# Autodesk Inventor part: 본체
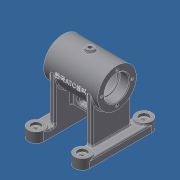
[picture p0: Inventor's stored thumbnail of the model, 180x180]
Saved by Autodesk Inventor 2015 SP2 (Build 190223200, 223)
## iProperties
Created: 2015-11
Part Number: 본체
Material: 일반
Document SubType Name: Modeling
Designer: AMC
Density: 1 g/cm^3
Appearance: 기본값
Author: AMC
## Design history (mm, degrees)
sketch "스케치1"
  geometry: C1 r 25 at (0, 0); 1 further point
  constraints: 1 centre point, 1 coincident
  dimensions: "d0" = 50 diameter of C1
extrude "돌출1" new body sketch "스케치1" stored distance "d1" = 70; taper "d2" = 0 deg
node "작업 평면1"
sketch "스케치2"
  geometry: C1 r 5 at (0, 0); 1 further point
  constraints: 1 centre point, 1 coincident
  dimensions: "d4" = 10 diameter of C1
extrude "돌출2" join sketch "스케치2" stored distance "d5" = 70; taper "d6" = 0 deg
node "작업 평면2"
sketch "스케치3"
  geometry: L1 (25, 0)-(-25, 0); L2 (-25, 0)-(-25, -68); L3 (-25, -68)-(25, -68); L4 (25, -68)-(25, 0); L5 (0, 0)-(0, 5.329)
  constraints: 10 end point, 2 parallel, 1 horizontal, 1 midpoint, 1 perpendicular, 1 vertical, 1 other
  dimensions: "d8" = 50 distance of L1.start L1.end; "d11" = 68 distance from line of L3 L5.start
extrude "돌출3" join sketch "스케치3" distance "d12" = 8; taper "d13" = 0 deg
sketch "스케치4"
  geometry: L1 (65, 10)-(-15, 10); L2 (65, 20)-(-15, 20); L3 (-15, 0)-(65, 0); L4 (0, 0)-(50, 0) reference; A1 r 10 centre (65, 10) between (65, 0) and (65, 20); A2 r 10 centre (-15, 10) between (-15, 20) and (-15, 0); 2 further points
  constraints: 8 end point, 4 point on circle, 4 tangent, 2 centre point, 1 collinear, 1 horizontal, 1 midpoint, 1 parallel
  dimensions: "d14" = 80 distance of L1.start L1.end; "d16" = 20 diameter of A1; "d17" = 40 horizontal distance of L1.start point (25, -20)
extrude "돌출4" join sketch "스케치4" distance "d18" = 10; taper "d19" = 0 deg
sketch "스케치6"
  geometry: C1 r 10 at (-65, 10); C2 r 10 at (15, 10); C3 r 10 at (15, -50); C4 r 10 at (-65, -50); A1 r 10 centre (-65, 10) between (-65, 20) and (-65, 0) reference; A2 r 10 centre (15, 10) between (15, 0) and (15, 20) reference; A3 r 10 centre (15, -50) between (15, -60) and (15, -40) reference; A4 r 10 centre (-65, -50) between (-65, -40) and (-65, -60) reference; 1 further point
  constraints: 4 centre point, 4 concentric
  dimensions: "d29" = 20 diameter of C1; "d32" = 20 diameter of C2; "d33" = 20 diameter of C3; "d34" = 20 diameter of C4
extrude "돌출6" join sketch "스케치6" distance "d30" = 3; taper "d31" = 0 deg
node "작업 평면5"
  node "작업 평면4"
sketch "스케치7"
  geometry: 1 further point
sketch "스케치8"
  geometry: C1 r 6 at (0, 0); 1 further point
  constraints: 1 centre point, 1 coincident
  dimensions: "d37" = 12 diameter of C1
extrude "돌출7" join sketch "스케치8" stored distance "d38" = 3; taper "d39" = 0 deg
hole "구멍1" diameter "d42" = 32; stored, may be unused: countersink angle "d46" = 90 deg, drill point angle "d48" = 0 deg; dims "d43" = 6, "d44" = 4, "d45" = 2, "d47" = 12, "d51" = 10, "d52" = 10
hole "구멍2" diameter "d53" = 32; stored, may be unused: countersink angle "d57" = 90 deg, drill point angle "d59" = 0 deg; dims "d49" = 10, "d50" = 10, "d54" = 6, "d55" = 4, "d56" = 2, "d58" = 12
hole "구멍3" diameter "d62" = 28; stored, may be unused: countersink angle "d66" = 90 deg, drill point angle "d68" = 0 deg; dims "d63" = 6, "d64" = 4, "d65" = 2, "d67" = 2, "d69" = 10, "d70" = 10
hole "구멍4" diameter "d73" = 28; stored, may be unused: countersink angle "d77" = 90 deg, drill point angle "d79" = 0 deg; dims "d71" = 10, "d72" = 10, "d74" = 6, "d75" = 4, "d76" = 2, "d78" = 2
hole "구멍5" diameter "d82" = 42; stored, may be unused: countersink angle "d86" = 90 deg, drill point angle "d88" = 0 deg; dims "d80" = 10, "d81" = 10, "d83" = 6, "d84" = 4, "d85" = 2, "d87" = 42
hole "구멍6" diameter "d91" = 6; stored, may be unused: countersink angle "d95" = 90 deg, drill point angle "d97" = 0 deg; dims "d92" = 6, "d93" = 12, "d94" = 4, "d96" = 42, "d127" = 10, "d128" = 10
hole "구멍7" diameter "d100" = 6; stored, may be unused: countersink angle "d104" = 90 deg, drill point angle "d106" = 0 deg; dims "d98" = 10, "d99" = 10, "d101" = 6, "d102" = 12, "d103" = 4, "d105" = 42
hole "구멍8" diameter "d109" = 6; stored, may be unused: countersink angle "d113" = 90 deg, drill point angle "d115" = 0 deg; dims "d107" = 10, "d108" = 10, "d110" = 6, "d111" = 12, "d112" = 4, "d114" = 42
hole "구멍9" diameter "d118" = 6; stored, may be unused: countersink angle "d122" = 90 deg, drill point angle "d124" = 0 deg; dims "d116" = 10, "d117" = 10, "d119" = 6, "d120" = 12, "d121" = 4, "d123" = 42
hole "구멍10" diameter "d129" = 4.917; stored, may be unused: countersink angle "d133" = 90 deg, drill point angle "d135" = 0 deg; dims "d125" = 10, "d126" = 10, "d130" = 12, "d131" = 1, "d132" = 4, "d134" = 17.1
hole "구멍11" diameter "d138" = 4.917; stored, may be unused: countersink angle "d142" = 90 deg, drill point angle "d144" = 0 deg; dims "d136" = 10, "d137" = 10, "d139" = 12, "d140" = 1, "d141" = 4, "d143" = 17.1
sketch "스케치9" dims "d145" = 40
  geometry: 3 further points
  constraints: 1 coincident, 1 vertical alignment, 2 other
hole "구멍12" sketch "스케치9" at (0, -20) diameter "d146" = 3.459; stored, may be unused: countersink angle "d150" = 90 deg, drill point angle "d152" = 118 deg; dims "d147" = 8, "d148" = 1, "d149" = 4, "d151" = 10
node "작업 평면7"
sketch "스케치10"
  geometry: L1 (-20.739, 3.002)-(20.739, 3.002); L2 (20.739, 3.002)-(20.739, -3.002); L3 (20.739, -3.002)-(-20.739, -3.002); L4 (-20.739, -3.002)-(-20.739, 3.002); L5 (-20.739, 0)-(20.739, 0); L6 (0, 3.002)-(0, -3.002); L7 (20, -25)-(-20, -25) reference; L8 (-35, 25)-(-35, -25) reference; 1 further point
  constraints: 4 end point, 4 midpoint, 2 other
  dimensions: "d157" = 41.47897 distance of L1.start L1.end; "d158" = 6.00407 distance of L1.end L2.end; "d159" = 25 distance between parallel lines of L5 L7; "d160" = 35 distance between parallel lines of L8 L6
feature "엠보싱1" sketch "스케치10" dims "d161" = 0.5, "d162" = 0
fillet "모깎기1" dims "d163" = 0.3
fillet "모깎기2" dims "d164" = 0.3
chamfer "모따기1" distance "d165" = 1; stored, may be unused: second distance "d166" = 2, angle "d167" = 45 deg
chamfer "모따기2" distance "d168" = 1; stored, may be unused: second distance "d169" = 2, angle "d170" = 45 deg
fillet "모깎기5" dims "d173" = 2
fillet "모깎기7" dims "d175" = 2
fillet "모깎기8" dims "d176" = 2
fillet "모깎기10" dims "d178" = 2
fillet "모깎기11" dims "d179" = 2
sketch "스케치11"
  geometry: L1 (-20, -22.177)-(20, -22.177); L2 (20, -22.177)-(20, -45); L3 (20, -45)-(-20, -45); L4 (-20, -45)-(-20, -22.177); L5 (-20, -14.142)-(-20, -56) reference; L6 (20, -56)-(20, -14.142) reference; L7 (-8, -35)-(8, -35); L8 (-8, -31.5)-(8, -31.5); L9 (8, -38.5)-(-8, -38.5); A1 r 3.5 centre (-8, -35) between (-8, -31.5) and (-8, -38.5); A2 r 3.5 centre (8, -35) between (8, -38.5) and (8, -31.5); 2 further points
  constraints: 16 end point, 4 point on circle, 4 tangent, 3 parallel, 2 centre point, 2 collinear, 2 horizontal, 1 midpoint, 1 perpendicular
  dimensions: "d182" = 3.5 radius of A2; "d183" = 23 dimension on A1 A2; "d185" = 45 distance from line of point (0, 0) L3; "d186" = 10 distance between parallel lines of L3 L7
extrude "돌출8" join sketch "스케치11" stored distance "d187" = 8; taper "d188" = 0 deg
fillet "모깎기12" dims "d189" = 2
fillet "모깎기13" dims "d190" = 2
node "솔리드1"
mirror "대칭1"
mirror "대칭2"
pattern_circular "원형 패턴1" dims angle "d154" = 360 deg
mirror "대칭3"
node "작업 평면3"
node "작업 평면6"
other parameters: "d3" = 28, "d35" = -30 deg, "d36" = -28, "d156" = -53.5
